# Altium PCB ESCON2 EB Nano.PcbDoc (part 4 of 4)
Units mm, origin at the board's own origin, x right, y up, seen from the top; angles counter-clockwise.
Board outline 67 x 70 mm, 6 copper layers (Top Side, Mid Layer 1, Mid Layer 2, Mid Layer 5, Mid Layer 6, Bottom Side), stack 1.48 mm thick; 293 components, 114 nets, 848 pads, 2005 vias.
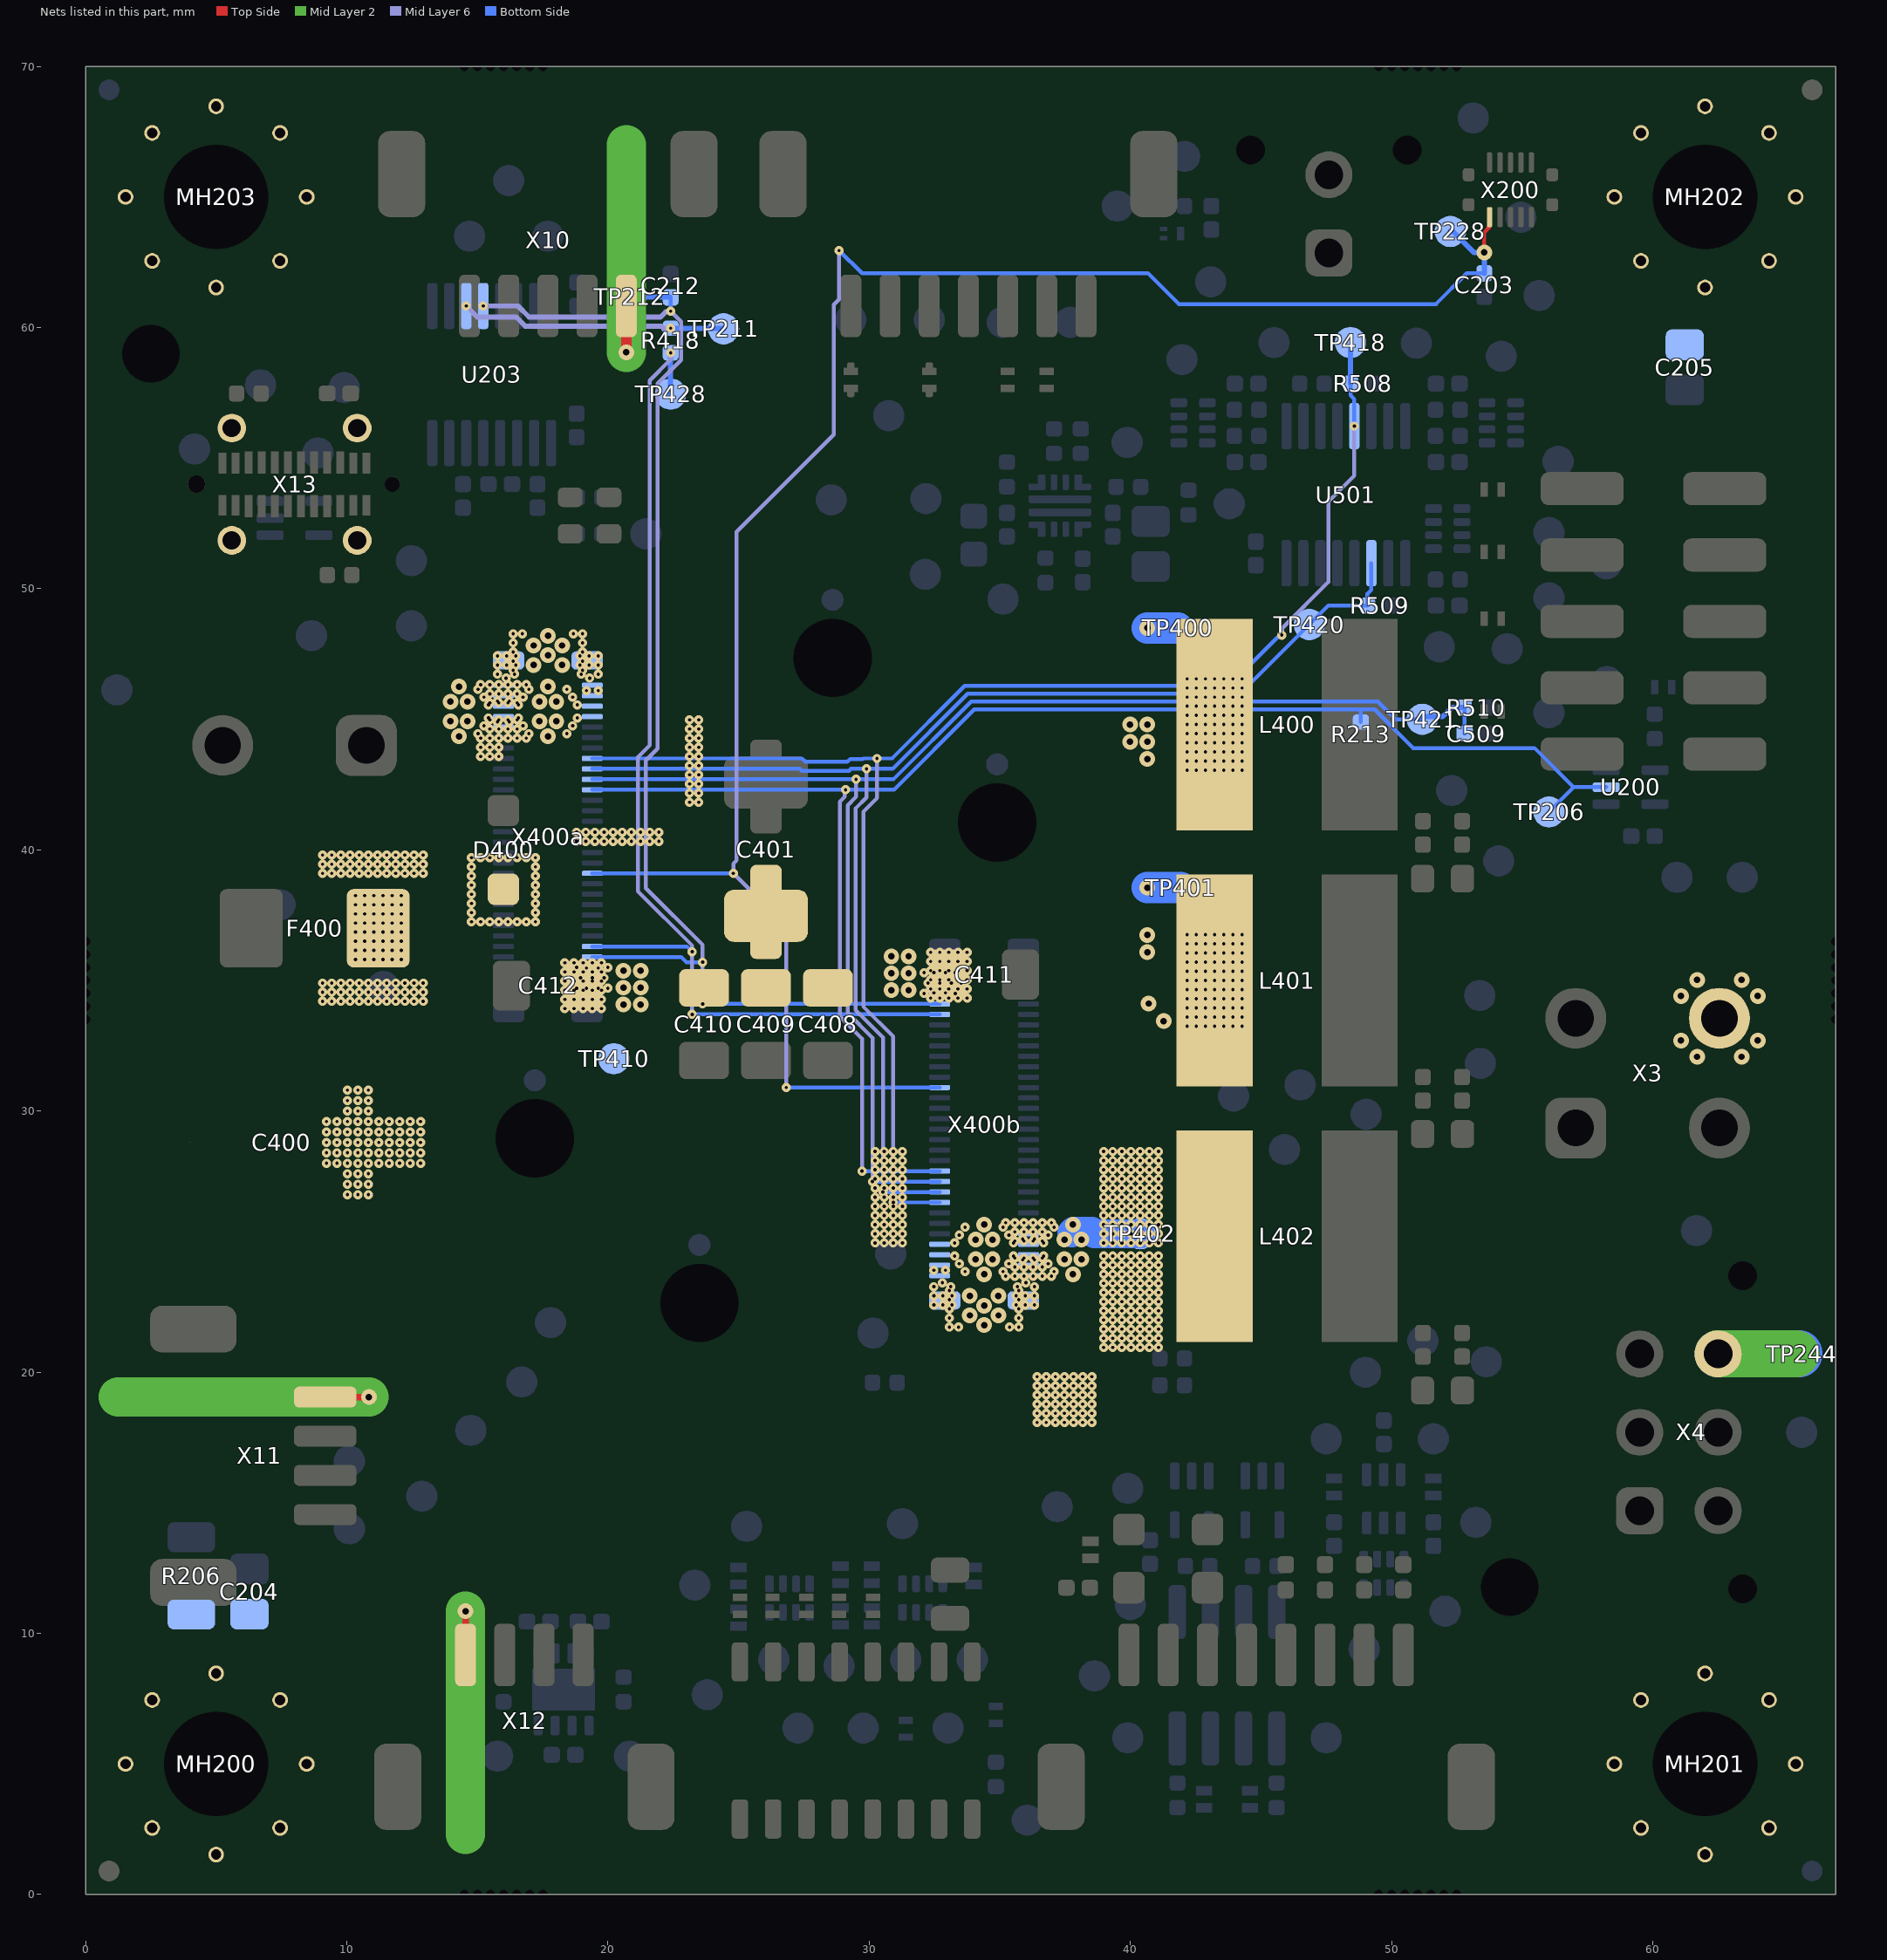
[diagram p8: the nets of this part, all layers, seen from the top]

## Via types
v1: diameter 0.35, hole 0.125, Top Side to Mid Layer 1, tented both sides, 1153 vias
v2: diameter 0.6, hole 0.25, Top Side to Bottom Side, 489 vias
v3: diameter 0.35, hole 0.125, Mid Layer 6 to Bottom Side, tented both sides, 363 vias

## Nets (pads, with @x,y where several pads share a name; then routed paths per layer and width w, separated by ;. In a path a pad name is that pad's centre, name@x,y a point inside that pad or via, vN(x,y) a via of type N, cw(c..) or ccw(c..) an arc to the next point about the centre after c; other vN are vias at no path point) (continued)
S2_B_HsDgin2: R508.1 TP418.1 U501.5 X400a.16 X400b.16 | length 60.1
  Mid Layer 6 w0.15: v3(30.3,43.5) 30.3,41.981 29.775,41.456 29.775,34.001 30.925,32.851 v3(30.925,26.5) ; v3(45.8,48.225) 45.808,48.233 45.808,48.483 47.575,50.25 47.575,53.325 48.575,54.325 v3(48.575,56.225)
  Bottom Side w0.15: X400a.16@19.4,43.5 27.429,43.5 27.559,43.37 29.168,43.37 29.273,43.475 29.749,43.475 29.774,43.5 v3(30.3,43.5) 30.877,43.5 33.652,46.275 43.775,46.275 45.63,48.13 45.651,48.13 45.746,48.225 v3(45.8,48.225) ; v3(30.925,26.5) 31.325,26.5 X400b.16@32.7,26.5 ; R508.1@48.43,57.85 48.43,57.395 48.575,57.25 v3(48.575,56.225)
  Bottom Side w0.2: TP418.1@48.425,59.175 48.43,59.17 R508.1@48.43,57.85
S2_Clock: R213.2 TP206.1 U200.2 X400a.22 X400b.22 | length 61.2
  Mid Layer 6 w0.15: v3@29.15,42.3 29.062,42.212 29.062,42.032 28.875,41.845 28.875,33.625 29.725,32.775 v3(29.725,27.7)
  Bottom Side w0.15: X400a.22@19.4,42.3 30.953,42.3 34.028,45.375 48.825,45.375 ; v3(29.725,27.7) X400b.22@32.7,27.7 ; R213.2@48.825,44.895 48.825,45.375 ; TP206.1@56.025,41.45 56.972,42.397 56.972,42.4 ; U200.2@58.215,42.4 56.972,42.4 ; 48.825,45.375 49.35,45.375 50.825,43.9 55.472,43.9 56.972,42.4
  other v3: 29.1,42.3
S2_Data_HsDgin4: C509.1 R510.2 TP421.1 X400a.20 X400b.20 | length 54.6
  Mid Layer 6 w0.15: v3(29.5,42.7) 29.5,42.032 29.175,41.707 29.175,33.751 30.125,32.801 v3(30.125,27.3)
  Bottom Side w0.15: X400a.20@19.4,42.7 29.55,42.7 30.928,42.7 33.903,45.675 49.475,45.675 50.15,45 TP421.1@51.175,45 ; v3(30.125,27.3) 30.525,27.3 X400b.20@32.7,27.3 ; R510.2@52.78,45.45 52.8,45.43 C509.1@52.8,44.45
  Bottom Side w0.2: TP421.1@51.175,45 51.274,45.099 51.949,45.099 52.3,45.45 R510.2@52.78,45.45
S2_I_HsDgin3: R509.1 TP420.1 U501.11 X400a.18 X400b.18 | length 53
  Mid Layer 6 w0.15: v3(29.9,43.1) 29.9,42.007 29.475,41.582 29.475,33.875 30.525,32.825 v3(30.525,26.9)
  Bottom Side w0.15: X400a.18@19.4,43.1 27.35,43.1 27.425,43.025 29.227,43.025 29.302,43.1 30.901,43.1 33.776,45.975 44.2,45.975 TP420.1@46.85,48.625 47.575,49.35 R509.1@49.08,49.35 49.075,49.355 49.075,49.8 49.225,49.95 U501.11@49.225,50.975 ; v3(30.525,26.9) 30.925,26.9 X400b.18@32.7,26.9
SGND: C204.2 C205.2 MH200.2 MH200.3 MH200.4 MH200.5 MH200.6 MH200.7 MH200.8 MH200.9 MH201.2 MH201.3 MH201.4 MH201.5 MH201.6 MH201.7 MH201.8 MH201.9 MH202.2 MH202.3 MH202.4 MH202.5 MH202.6 MH202.7 MH202.8 MH202.9 MH203.2 MH203.3 MH203.4 MH203.5 MH203.6 MH203.7 MH203.8 MH203.9 R206.2 TP244.1 X3.4 X4.6 X10.5 X11.4 X12.4 X13.S1 X13.S2 X13.S3 X13.S4 | length 35.5
  Top Side w0.25: X11.4@9.65,19.05 v2@10.85,19.05 ; X12.4@14.55,9.65 v2(14.55,10.85)
  Top Side w0.4: v2(20.7,59.05) X10.5@20.7,60
  Mid Layer 2 w1.5: 1.25,19.05 v2(10.85,19.05) ; 14.55,2.3 v2(14.55,10.85) ; v2(20.7,59.05) 20.7,67
  Mid Layer 2 w1.8: X4.6@62.5,20.7 65.475,20.7
  Bottom Side w1.8: X4.6@62.5,20.7 TP244.1@65.6,20.7
  other v2: 61.7,32.078 63.4,32.078 61.078,32.7 64.022,32.7 61.078,34.4 64.022,34.4 61.7,35.022 63.4,35.022
SYS_/Reset: C203.2 TP228.1 X200.10 X400a.38 X400b.38 | length 75.7
  Top Side w0.15: v2(53.55,62.875) 53.55,63.645 53.75,63.845 X200.10@53.75,64.23
  Mid Layer 6 w0.15: v3(26.825,30.9) 26.825,37.075 v3(24.8,39.1) 24.8,39.475 24.919,39.594 24.919,52.172 28.65,55.903 28.65,60.875 28.85,61.075 v3(28.85,62.95)
  Bottom Side w0.15: X400a.38@19.4,39.1 v3(24.8,39.1) ; v3(26.825,30.9) X400b.38@32.7,30.9 ; v3(28.85,62.95) 29.726,62.074 40.676,62.074 41.85,60.9 51.7,60.9 52.875,62.075 C203.2@53.55,62.075
  Bottom Side w0.2: TP228.1@52.25,63.675 52.35,63.675 53.15,62.875 v2(53.55,62.875) C203.2@53.55,62.075
U: L400.1 TP400.1 X400a.0a X400a.1 X400a.2 X400a.4 X400b.0a X400b.1 X400b.2 X400b.4 | length 1.2
  Bottom Side w1.2: v2(40.65,48.5) TP400.1@41.8,48.5
  other v1: 36.425,18.075 36.775,18.075 37.125,18.075 37.475,18.075 37.825,18.075 38.175,18.075 38.525,18.075 36.425,18.425 36.775,18.425 37.125,18.425 37.475,18.425 37.825,18.425 38.175,18.425 38.525,18.425 36.425,18.775 36.775,18.775 37.125,18.775 37.475,18.775 37.825,18.775 38.175,18.775 38.525,18.775 36.425,19.125 36.775,19.125 37.125,19.125 37.475,19.125 37.825,19.125 38.175,19.125 38.525,19.125 36.425,19.475 36.775,19.475 37.125,19.475 37.475,19.475 37.825,19.475 38.175,19.475 38.525,19.475 36.425,19.825 36.775,19.825 37.125,19.825 37.475,19.825 37.825,19.825 38.175,19.825 38.525,19.825 33.075,21.725 33.425,21.725 35.375,21.725 35.725,21.725 33.075,22.075 35.725,22.075 33.075,22.425 35.725,22.425 33.075,22.775 35.725,22.775 33.075,23.125 35.725,23.125 42.175,43.05 42.525,43.05 42.875,43.05 43.225,43.05 43.575,43.05 43.925,43.05 44.275,43.05 42.175,43.4 42.525,43.4 42.875,43.4 43.225,43.4 43.575,43.4 43.925,43.4 44.275,43.4 42.175,43.75 42.525,43.75 42.875,43.75 43.225,43.75 43.575,43.75 43.925,43.75 44.275,43.75 42.175,44.1 42.525,44.1 42.875,44.1 43.225,44.1 43.575,44.1 43.925,44.1 44.275,44.1 42.175,44.45 42.525,44.45 42.875,44.45 43.225,44.45 43.575,44.45 43.925,44.45 44.275,44.45 42.175,44.8 42.525,44.8 42.875,44.8 43.225,44.8 43.575,44.8 43.925,44.8 44.275,44.8 42.175,45.15 42.525,45.15 42.875,45.15 43.225,45.15 43.575,45.15 43.925,45.15 44.275,45.15 42.175,45.5 42.525,45.5 42.875,45.5 43.225,45.5 43.575,45.5 43.925,45.5 44.275,45.5 42.175,45.85 42.525,45.85 42.875,45.85 43.225,45.85 43.575,45.85 43.925,45.85 44.275,45.85 42.175,46.2 42.525,46.2 42.875,46.2 43.225,46.2 43.575,46.2 43.925,46.2 44.275,46.2 42.175,46.55 42.525,46.55 42.875,46.55 43.225,46.55 43.575,46.55 43.925,46.55 44.275,46.55 16.375,46.875 19.025,46.875 16.375,47.225 19.025,47.225 16.375,47.575 19.025,47.575 16.375,47.925 19.025,47.925 16.375,48.275 16.725,48.275 18.675,48.275 19.025,48.275
  other v2: 34.4,21.8 33.85,22.175 34.95,22.175 34.4,22.55 33.85,22.925 34.945,22.925 40.65,43.48 39.99,44.14 40.65,44.14 39.99,44.8 40.65,44.8 17.155,47.075 18.25,47.075 17.7,47.45 17.15,47.825 18.25,47.825 17.7,48.2
  other v3: 32.475,22.575 32.825,22.575 33.175,22.575 35.625,22.575 35.975,22.575 36.325,22.575 32.475,22.925 32.825,22.925 33.175,22.925 35.625,22.925 35.975,22.925 36.325,22.925 32.475,23.275 33.125,23.275 35.675,23.275 36.325,23.275 32.8,23.425 36,23.425 32.475,23.9 32.925,23.9 19.175,46.1 19.625,46.1 16.1,46.575 19.3,46.575 15.775,46.725 16.425,46.725 18.975,46.725 19.625,46.725 15.775,47.075 16.125,47.075 16.475,47.075 18.925,47.075 19.275,47.075 19.625,47.075 15.775,47.425 16.125,47.425 16.475,47.425 18.925,47.425 19.275,47.425 19.625,47.425
UART_RxD: C212.2 TP212.1 U203.12 X400a.54 X400b.54 | length 51.1
  Mid Layer 6 w0.15: v3(22.4,60.625) 22.8,60.225 22.8,58.75 21.9,57.85 21.9,43.878 21.45,43.428 21.45,38.532 23.625,36.357 v3(23.625,35.7) v3(23.625,34.1)
  Mid Layer 6 w0.2: v3(15.225,60.825) 16.558,60.825 16.983,60.4 22.011,60.4 22.207,60.596 22.371,60.596 v3(22.4,60.625)
  Bottom Side w0.15: X400a.54@19.4,35.9 22.8,35.9 23,35.7 v3(23.625,35.7) ; C212.2@22.375,61.175 C212.2@22.4,61.15 v3(22.4,60.625) ; v3(23.625,34.1) X400b.54@32.7,34.1
  Bottom Side w0.2: TP212.1@20.825,61.175 C212.2@22.375,61.175
UART_TxD: R418.1 TP211.1 U203.11 | length 10.2
  Mid Layer 6 w0.2: v3(14.575,60.825) 15,60.4 16.488,60.4 16.838,60.05 22.047,60.05 22.127,59.97 v3(22.4,59.97)
  Bottom Side w0.2: v3(22.4,59.97) 24.405,59.97 TP211.1@24.425,59.95
UART_TxD_n: R418.2 TP428.1 X400a.52 X400b.52 | length 41.5
  Mid Layer 6 w0.15: v3(22.4,59.03) 22.395,59.025 22.395,58.77 21.6,57.975 21.6,44.002 21.15,43.552 21.15,38.408 23.225,36.333 v3(23.225,36.1) v3(23.225,33.7)
  Bottom Side w0.15: X400a.52@19.4,36.3 23.025,36.3 v3@23.125,36.2 ; v3(23.225,33.7) X400b.52@32.7,33.7
  Bottom Side w0.2: TP428.1@22.4,57.45 v3(22.4,59.03)
V: L401.1 TP401.1 X400a.3 X400a.5 X400a.6 X400b.3 X400b.5 X400b.6 | length 1.3
  Bottom Side w1.2: v2(40.65,38.55) TP401.1@41.925,38.55
  other v1: 38.975,20.95 39.325,20.95 39.675,20.95 40.025,20.95 40.375,20.95 40.725,20.95 41.075,20.95 38.975,21.3 39.325,21.3 39.675,21.3 40.025,21.3 40.375,21.3 40.725,21.3 41.075,21.3 38.975,21.65 39.325,21.65 39.675,21.65 40.025,21.65 40.375,21.65 40.725,21.65 41.075,21.65 38.975,22 39.325,22 39.675,22 40.025,22 40.375,22 40.725,22 41.075,22 38.975,22.35 39.325,22.35 39.675,22.35 40.025,22.35 40.375,22.35 40.725,22.35 41.075,22.35 38.975,22.7 39.325,22.7 39.675,22.7 40.025,22.7 40.375,22.7 40.725,22.7 41.075,22.7 38.975,23.05 39.325,23.05 39.675,23.05 40.025,23.05 40.375,23.05 40.725,23.05 41.075,23.05 38.975,23.4 39.325,23.4 39.675,23.4 40.025,23.4 40.375,23.4 40.725,23.4 41.075,23.4 35.225,23.675 35.575,23.675 35.925,23.675 36.275,23.675 36.625,23.675 36.975,23.675 38.975,23.75 39.325,23.75 39.675,23.75 40.025,23.75 40.375,23.75 40.725,23.75 41.075,23.75 35.575,24.025 35.925,24.025 36.275,24.025 36.625,24.025 38.975,24.1 39.325,24.1 39.675,24.1 40.025,24.1 40.375,24.1 40.725,24.1 41.075,24.1 35.575,24.375 35.925,24.375 36.275,24.375 36.625,24.375 38.975,24.45 39.325,24.45 39.675,24.45 40.025,24.45 40.375,24.45 40.725,24.45 41.075,24.45 42.175,33.25 42.525,33.25 42.875,33.25 43.225,33.25 43.575,33.25 43.925,33.25 44.275,33.25 42.175,33.6 42.525,33.6 42.875,33.6 43.225,33.6 43.575,33.6 43.925,33.6 44.275,33.6 42.175,33.95 42.525,33.95 42.875,33.95 43.225,33.95 43.575,33.95 43.925,33.95 44.275,33.95 42.175,34.3 42.525,34.3 42.875,34.3 43.225,34.3 43.575,34.3 43.925,34.3 44.275,34.3 42.175,34.65 42.525,34.65 42.875,34.65 43.225,34.65 43.575,34.65 43.925,34.65 44.275,34.65 42.175,35 42.525,35 42.875,35 43.225,35 43.575,35 43.925,35 44.275,35 42.175,35.35 42.525,35.35 42.875,35.35 43.225,35.35 43.575,35.35 43.925,35.35 44.275,35.35 42.175,35.7 42.525,35.7 42.875,35.7 43.225,35.7 43.575,35.7 43.925,35.7 44.275,35.7 42.175,36.05 42.525,36.05 42.875,36.05 43.225,36.05 43.575,36.05 43.925,36.05 44.275,36.05 42.175,36.4 42.525,36.4 42.875,36.4 43.225,36.4 43.575,36.4 43.925,36.4 44.275,36.4 42.175,36.75 42.525,36.75 42.875,36.75 43.225,36.75 43.575,36.75 43.925,36.75 44.275,36.75 23.125,41.825 23.475,41.825 23.125,42.175 23.475,42.175 23.125,42.525 23.475,42.525 23.125,42.875 23.475,42.875 23.125,43.225 23.475,43.225 23.125,43.575 23.475,43.575 23.125,43.925 23.475,43.925 23.125,44.275 23.475,44.275 23.125,44.625 23.475,44.625 23.125,44.975 23.475,44.975 15.475,45.625 15.825,45.625 16.175,45.625 16.525,45.625 15.475,45.975 15.825,45.975 16.175,45.975 16.525,45.975 15.125,46.325 15.475,46.325 15.825,46.325 16.175,46.325 16.525,46.325 16.875,46.325
  other v2: 34.4,23.75 37.8,23.75 34.075,24.325 34.725,24.325 37.475,24.325 38.125,24.325 41.275,33.44 40.7,34.115 40.65,36.08 40.65,36.74 13.975,45.675 14.625,45.675 17.375,45.675 18.025,45.675 14.3,46.25 17.7,46.25
  other v3: 33.675,23.85 35.125,23.85 37.075,23.85 33.45,24.15 35.35,24.15 36.85,24.15 35.875,24.3 36.325,24.3 33.275,24.45 35.525,24.45 36.675,24.45 15.425,45.55 16.575,45.55 18.825,45.55 15.775,45.7 16.225,45.7 15.25,45.85 16.75,45.85 18.65,45.85 15.025,46.15 16.975,46.15 18.425,46.15
VP: C400.1 C401.1 C408.2 C409.2 C410.2 C411.2 C412.2 D400.1 F400.2 TP410.1 X400a.56 X400a.58 X400a.60 X400b.56 X400b.58 X400b.60
  other v1: 10.025,26.8 10.425,26.8 10.825,26.8 10.025,27.2 10.425,27.2 10.825,27.2 10.025,27.6 10.425,27.6 10.825,27.6 9.225,28 9.625,28 10.025,28 10.425,28 10.825,28 11.225,28 11.625,28 12.025,28 12.425,28 12.825,28 9.225,28.4 9.625,28.4 10.025,28.4 10.425,28.4 10.825,28.4 11.225,28.4 11.625,28.4 12.025,28.4 12.425,28.4 12.825,28.4 9.225,28.8 9.625,28.8 10.025,28.8 10.425,28.8 10.825,28.8 11.225,28.8 11.625,28.8 12.025,28.8 12.425,28.8 12.825,28.8 9.225,29.2 9.625,29.2 10.025,29.2 10.425,29.2 10.825,29.2 11.225,29.2 11.625,29.2 12.025,29.2 12.425,29.2 12.825,29.2 9.225,29.6 9.625,29.6 10.025,29.6 10.425,29.6 10.825,29.6 11.225,29.6 11.625,29.6 12.025,29.6 12.425,29.6 12.825,29.6 10.025,30 10.425,30 10.825,30 10.025,30.4 10.425,30.4 10.825,30.4 10.025,30.8 10.425,30.8 10.825,30.8 18.35,33.925 18.7,33.925 19.05,33.925 19.4,33.925 19.75,33.925 9.075,34.2 9.425,34.2 9.775,34.2 10.125,34.2 10.475,34.2 10.825,34.2 11.175,34.2 11.525,34.2 11.875,34.2 12.225,34.2 12.575,34.2 12.925,34.2 18.35,34.275 18.7,34.275 19.05,34.275 19.4,34.275 19.75,34.275 32.35,34.325 32.7,34.325 33.05,34.325 33.4,34.325 33.75,34.325 9.075,34.55 9.425,34.55 9.775,34.55 10.125,34.55 10.475,34.55 10.825,34.55 11.175,34.55 11.525,34.55 11.875,34.55 12.225,34.55 12.575,34.55 12.925,34.55 18.35,34.625 18.7,34.625 19.05,34.625 19.4,34.625 19.75,34.625 32.35,34.675 32.7,34.675 33.05,34.675 33.4,34.675 33.75,34.675 9.075,34.9 9.425,34.9 9.775,34.9 10.125,34.9 10.475,34.9 10.825,34.9 11.175,34.9 11.525,34.9 11.875,34.9 12.225,34.9 12.575,34.9 12.925,34.9 18.35,34.975 18.7,34.975 19.05,34.975 19.4,34.975 19.75,34.975 32.35,35.025 32.7,35.025 33.05,35.025 33.4,35.025 33.75,35.025 18.35,35.325 18.7,35.325 19.05,35.325 19.4,35.325 19.75,35.325 32.35,35.375 32.7,35.375 33.05,35.375 33.4,35.375 33.75,35.375 18.35,35.675 18.7,35.675 19.05,35.675 19.4,35.675 19.75,35.675 32.35,35.725 32.7,35.725 33.05,35.725 33.4,35.725 33.75,35.725 10.335,35.8 10.685,35.8 11.035,35.8 11.385,35.8 11.735,35.8 12.085,35.8 32.35,36.075 32.7,36.075 33.05,36.075 33.4,36.075 33.75,36.075 10.335,36.15 10.685,36.15 11.035,36.15 11.385,36.15 11.735,36.15 12.085,36.15 10.335,36.5 10.685,36.5 11.035,36.5 11.385,36.5 11.735,36.5 12.085,36.5 10.335,36.85 10.685,36.85 11.035,36.85 11.385,36.85 11.735,36.85 12.085,36.85 10.335,37.2 10.685,37.2 11.035,37.2 11.385,37.2 11.735,37.2 12.085,37.2 14.775,37.25 15.125,37.25 15.475,37.25 15.825,37.25 16.175,37.25 16.525,37.25 16.875,37.25 17.225,37.25 10.335,37.55 10.685,37.55 11.035,37.55 11.385,37.55 11.735,37.55 12.085,37.55 14.775,37.6 17.225,37.6 10.335,37.9 10.685,37.9 11.035,37.9 11.385,37.9 11.735,37.9 12.085,37.9 14.775,37.95 17.225,37.95 10.335,38.25 10.685,38.25 11.035,38.25 11.385,38.25 11.735,38.25 12.085,38.25 14.775,38.3 17.225,38.3 14.775,38.65 17.225,38.65 14.775,39 17.225,39 9.075,39.1 9.425,39.1 9.775,39.1 10.125,39.1 10.475,39.1 10.825,39.1 11.175,39.1 11.525,39.1 11.875,39.1 12.225,39.1 12.575,39.1 12.925,39.1 14.775,39.35 17.225,39.35 9.075,39.45 9.425,39.45 9.775,39.45 10.125,39.45 10.475,39.45 10.825,39.45 11.175,39.45 11.525,39.45 11.875,39.45 12.225,39.45 12.575,39.45 12.925,39.45 14.775,39.7 15.125,39.7 15.475,39.7 15.825,39.7 16.175,39.7 16.525,39.7 16.875,39.7 17.225,39.7 9.075,39.8 9.425,39.8 9.775,39.8 10.125,39.8 10.475,39.8 10.825,39.8 11.175,39.8 11.525,39.8 11.875,39.8 12.225,39.8 12.575,39.8 12.925,39.8
  other v2: 20.59,34.075 21.25,34.075 30.85,34.625 31.51,34.625 20.59,34.725 21.25,34.725 30.85,35.275 31.51,35.275 20.59,35.375 21.25,35.375 30.85,35.925 31.51,35.925
  other v3: 32.1,34.5 33.3,34.5 32.475,34.525 32.925,34.525 18.8,34.7 19.175,34.7 19.625,34.7 20,34.7 32.25,34.9 32.7,34.9 33.15,34.9 33.525,34.9 18.575,35.1 18.95,35.1 19.4,35.1 19.85,35.1 32.1,35.3 32.475,35.3 32.925,35.3 33.3,35.3 19.175,35.475 19.625,35.475 18.8,35.5 20,35.5
W: L402.1 TP402.1 X400a.7 X400a.8 X400a.9 X400b.7 X400b.8 X400b.9 | length 2.7
  Bottom Side w1.1: 37.75,25.325 37.825,25.4 38.525,25.4 38.625,25.3 v1(40.375,25.3)
  other v1: 30.225,24.95 30.575,24.95 30.925,24.95 31.275,24.95 38.975,24.95 39.325,24.95 39.675,24.95 40.025,24.95 40.375,24.95 40.725,24.95 41.075,24.95 35.575,25.025 35.925,25.025 36.275,25.025 36.625,25.025 30.225,25.3 30.575,25.3 30.925,25.3 31.275,25.3 38.975,25.3 39.325,25.3 39.675,25.3 40.025,25.3 40.725,25.3 41.075,25.3 35.575,25.375 35.925,25.375 36.275,25.375 36.625,25.375 30.225,25.65 30.575,25.65 30.925,25.65 31.275,25.65 38.975,25.65 39.325,25.65 39.675,25.65 40.025,25.65 40.375,25.65 40.725,25.65 41.075,25.65 35.225,25.725 35.575,25.725 35.925,25.725 36.275,25.725 36.625,25.725 36.975,25.725 30.225,26 30.575,26 30.925,26 31.275,26 38.975,26 39.325,26 39.675,26 40.025,26 40.375,26 40.725,26 41.075,26 30.225,26.35 30.575,26.35 30.925,26.35 31.275,26.35 38.975,26.35 39.325,26.35 39.675,26.35 40.025,26.35 40.375,26.35 40.725,26.35 41.075,26.35 30.225,26.7 30.575,26.7 30.925,26.7 31.275,26.7 38.975,26.7 39.325,26.7 39.675,26.7 40.025,26.7 40.375,26.7 40.725,26.7 41.075,26.7 30.225,27.05 30.575,27.05 30.925,27.05 31.275,27.05 38.975,27.05 39.325,27.05 39.675,27.05 40.025,27.05 40.375,27.05 40.725,27.05 41.075,27.05 30.225,27.4 30.575,27.4 30.925,27.4 31.275,27.4 38.975,27.4 39.325,27.4 39.675,27.4 40.025,27.4 40.375,27.4 40.725,27.4 41.075,27.4 30.225,27.75 30.575,27.75 30.925,27.75 31.275,27.75 38.975,27.75 39.325,27.75 39.675,27.75 40.025,27.75 40.375,27.75 40.725,27.75 41.075,27.75 30.225,28.1 30.575,28.1 30.925,28.1 31.275,28.1 38.975,28.1 39.325,28.1 39.675,28.1 40.025,28.1 40.375,28.1 40.725,28.1 41.075,28.1 30.225,28.45 30.575,28.45 30.925,28.45 31.275,28.45 38.975,28.45 39.325,28.45 39.675,28.45 40.025,28.45 40.375,28.45 40.725,28.45 41.075,28.45 18.8,40.325 19.15,40.325 19.5,40.325 19.85,40.325 20.2,40.325 20.55,40.325 20.9,40.325 21.25,40.325 21.6,40.325 21.95,40.325 18.8,40.675 19.15,40.675 19.5,40.675 19.85,40.675 20.2,40.675 20.55,40.675 20.9,40.675 21.25,40.675 21.6,40.675 21.95,40.675 15.125,43.575 15.475,43.575 15.825,43.575 15.125,43.925 15.475,43.925 15.825,43.925 15.125,44.275 15.475,44.275 15.825,44.275 16.175,44.275 16.525,44.275 16.875,44.275 15.475,44.625 15.825,44.625 16.175,44.625 16.525,44.625 15.475,44.975 15.825,44.975 16.175,44.975 16.525,44.975
  other v2: 34.075,25.075 34.725,25.075 37.475,25.075 38.125,25.075 34.4,25.65 37.8,25.65 14.3,44.35 17.7,44.35 13.975,44.925 14.625,44.925 17.375,44.925 18.025,44.925
  other v3: 33.275,24.95 35.525,24.95 36.675,24.95 35.875,25.1 36.325,25.1 33.45,25.25 35.35,25.25 36.85,25.25 33.675,25.55 35.125,25.55 37.075,25.55 15.025,44.45 16.975,44.45 18.425,44.45 15.25,44.75 16.75,44.75 18.65,44.75 15.775,44.9 16.225,44.9 15.425,45.05 16.575,45.05 18.825,45.05
pads on no net: FD200.1 FD201.1 FD202.1 FD203.1 MH200.1 MH201.1 MH202.1 MH203.1 MH204.1 MH205.1 MP400.0 MP401.0 MP402.0 MP403.0 RN501.3 RN501.6 RN502.2 RN502.7 RN503.2 RN503.7 RN504.2 RN504.7 STEG200.0 STEG201.0 STEG202.0 STEG203.0 STEG204.0 STEG205.0 U200.1 U203.7 U203.9 U400.3 U400.4 U400.10 U501.13 U501.14 U501.15 X4.0 X5.9 X7.0 X8.0 X10.0 X11.0 X12.0 X13.0 X13.A2 X13.A3 X13.A8 X13.A10 X13.A11 X13.B2 X13.B3 X13.B8 X13.B10 X13.B11 X16.0 X200.0 X200.6 X200.7 X200.8

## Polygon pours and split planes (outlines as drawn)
GND on Bottom Side "B_GND-001" (solid, remove dead copper, pour order 415): 0,0 0,70 67,70 67,0
5V0 on Bottom Side "BOT_5V0" (solid, remove dead copper, pour order 412): 31.525,52.275 34.686,52.261 34.9,52.475 35.325,52.475 35.9,52.475 35.9,53.05 36.075,53.225 39.875,53.225 39.875,54.575 39.25,54.575 38.45,53.775 36.15,53.775 35.3,54.625 31.525,54.625
C_W2 on Bottom Side "BOT_C_W2-002" (solid, remove dead copper, pour order 314): 54.9,36.35 59.7,36.35 59.7,31.55 54.9,31.55
W on Bottom Side "B_W_n_2" (solid, remove dead copper, pour order 241): 38.475,25.425 38.475,24.775 32.3,24.775 32.3,25.425
W on Bottom Side "B_W_n" (solid, remove dead copper, pour order 82): 13.625,44.575 13.625,45.225 19.8,45.225 19.8,44.575
C_VP on Bottom Side "B_C_VP-001" (solid, remove dead copper, pour order 362): 7.9,41.2 0,41.2 0,46.8 7.9,46.8
SGND on Bottom Side "B_SGND-002" (solid, pour order 377): 1.53,5 2.55,7.45 5,8.47 7.45,7.45 8.47,5 8.476,5 8.476,7.849 8.475,7.85 7.45,11.4 0.5,11.4 0.5,5
SGND on Bottom Side "B_SGND-003" (solid, pour order 378): 65.47,65 64.45,62.55 62,61.53 59.55,62.55 58.53,65 58.524,65 58.524,62.15 59.95,58.75 66.5,58.75 66.5,65
SGND on Bottom Side "B_SGND-001" (solid, remove dead copper, pour order 372): 60.1,36.35 64.7,36.35 64.7,31.55 60.1,31.55
C_W3 on Bottom Side "BOT_C_W3-002" (solid, remove dead copper, pour order 318): 59.9,31.35 64.7,31.35 64.7,26.55 59.9,26.55
C_W1 on Bottom Side "BOT_C_W1-002" (solid, remove dead copper, pour order 248): 54.9,31.35 59.7,31.35 59.7,26.55 54.9,26.55
5V0_sensor1_2 on Bottom Side "B_5V0_sensor1_2-001" (solid, remove dead copper, pour order 5): 42.55,53.45 40.025,53.45 40.025,54.575 42.55,54.575
V on Bottom Side "B_V_n" (solid, remove dead copper, pour order 81): 18.288,46.55 18.875,45.963 18.875,45.375 16.525,45.375 16.525,45.962 17.113,46.55
V on Bottom Side "B_V_n" (solid, remove dead copper, pour order 83): 13.625,45.375 13.625,46.025 19.8,46.025 19.8,45.375
W on Bottom Side "B_W_n" (solid, remove dead copper, pour order 84): 17.113,44.05 16.525,44.638 16.525,45.225 18.875,45.225 18.875,44.638 18.287,44.05
W on Bottom Side "B_W_n" (solid, remove dead copper, pour order 85): 13.713,44.05 13.625,44.138 13.625,45.225 15.475,45.225 15.475,44.638 14.888,44.05
V on Bottom Side "B_V_n" (solid, remove dead copper, pour order 87): 13.713,46.55 13.625,46.462 13.625,45.375 15.475,45.375 15.475,45.962 14.888,46.55
U on Bottom Side "B_U_n" (solid, remove dead copper, pour order 147): 15.6,45.775 15.6,47.875 19.8,47.875 19.8,45.775
U on Bottom Side "B_U_n" (solid, remove dead copper, pour order 239): 18.163,48.525 18.875,47.813 18.875,47.55 16.525,47.55 16.525,47.813 17.238,48.525
V on Bottom Side "B_V_n_2" (solid, remove dead copper, pour order 240): 33.812,23.45 33.225,24.037 33.225,24.625 35.575,24.625 35.575,24.038 34.987,23.45
V on Bottom Side "B_V_n_2" (solid, remove dead copper, pour order 242): 38.475,24.625 38.475,23.975 32.3,23.975 32.3,24.625
W on Bottom Side "B_W_n_2" (solid, remove dead copper, pour order 247): 34.987,25.95 35.575,25.362 35.575,24.775 33.225,24.775 33.225,25.362 33.813,25.95
W on Bottom Side "B_W_n_2" (solid, remove dead copper, pour order 327): 38.387,25.95 38.475,25.862 38.475,24.775 36.625,24.775 36.625,25.362 37.212,25.95
V on Bottom Side "B_V_n_2" (solid, remove dead copper, pour order 329): 38.387,23.45 38.475,23.538 38.475,24.625 36.625,24.625 36.625,24.038 37.212,23.45
U on Bottom Side "B_U_n_2" (solid, remove dead copper, pour order 348): 36.5,24.225 36.5,22.125 32.3,22.125 32.3,24.225
U on Bottom Side "B_U_n_2" (solid, remove dead copper, pour order 356): 33.938,21.475 33.225,22.187 33.225,22.45 35.575,22.45 35.575,22.187 34.862,21.475
VP on Bottom Side "B_VP_n" (solid, remove dead copper, pour order 357): 21.55,31.4 19.625,31.4 19.625,33.775 17.775,33.775 17.775,35.675 21.55,35.675 21.55,33.775
GND on Bottom Side "B_GND_n" (solid, pour order 358): 17.625,35.675 17.625,33.775 13.85,33.775 13.85,35.675
VP on Bottom Side "B_VP_n_2" (solid, remove dead copper, pour order 359): 34.325,36.225 34.325,34.325 30.55,34.325 30.55,36.225
GND on Bottom Side "B_GND_n_2" (solid, pour order 360): 34.475,34.325 34.475,36.225 38.25,36.225 38.25,34.325
NetC415_2 on Bottom Side "BOT_5V0_sensor1_2" (solid, remove dead copper, pour order 411): 36.1,53.1 36.1,52.575 38.45,52.575 38.6,52.425 39.675,52.425 39.875,52.225 42.55,52.225 42.55,53.3 40.95,53.3 40.025,53.3 39,53.3 38.8,53.1
GND on Mid Layer 6 "M6_GND-001" (solid, remove dead copper, pour order 416): 0,0 0,70 67,70 67,0
5V0_sensor1_2 on Mid Layer 6 "M6_5V0_sensor1_2-001" (solid, remove dead copper, pour order 29): 43.9,51.875 43.075,51.05 41.225,51.05 41.225,52.075 42.547,52.075 42.55,52.072 42.55,53.45 40.025,53.45 40.025,54.625 43.075,54.625 43.9,53.8
NetC415_2 on Mid Layer 6 "M6_5V0_sensor1_2" (solid, remove dead copper, pour order 413): 36.1,53.1 36.1,52.575 38.45,52.575 38.8,52.225 39.875,52.225 42.55,52.225 42.55,53.3 40.95,53.3 40.025,53.3 39,53.3 38.8,53.1
W on Mid Layer 6 "M6_W_n" (solid, remove dead copper, pour order 72): 13.625,44.575 13.625,45.225 19.05,45.225 19.05,44.575
V on Mid Layer 6 "M6_V_n" (solid, remove dead copper, pour order 73): 13.625,45.375 13.625,46.025 18.8,46.025 18.8,45.375
W on Mid Layer 6 "M6_W_n" (solid, remove dead copper, pour order 75): 17.113,44.05 16.525,44.638 16.525,45.225 18.875,45.225 18.875,44.638 18.287,44.05
V on Mid Layer 6 "M6_V_n" (solid, remove dead copper, pour order 77): 18.288,46.55 19.05,45.788 19.05,45.375 16.525,45.375 16.525,45.962 17.113,46.55
W on Mid Layer 6 "M6_W_n" (solid, remove dead copper, pour order 78): 13.713,44.05 13.625,44.138 13.625,45.225 15.475,45.225 15.475,44.638 14.888,44.05
V on Mid Layer 6 "M6_V_n" (solid, remove dead copper, pour order 79): 13.713,46.55 13.625,46.462 13.625,45.375 15.475,45.375 15.475,45.962 14.888,46.55
U on Mid Layer 6 "M6_U_n" (solid, remove dead copper, pour order 159): 15.6,45.775 15.6,47.875 19.8,47.875 19.8,45.775
U on Mid Layer 6 "M6_U_n" (solid, remove dead copper, pour order 243): 18.163,48.525 18.875,47.813 18.875,47.55 16.525,47.55 16.525,47.813 17.238,48.525
W on Mid Layer 6 "M6_W_n_2" (solid, remove dead copper, pour order 244): 38.475,25.425 38.475,24.775 33.05,24.775 33.05,25.425
V on Mid Layer 6 "M6_V_n_2" (solid, remove dead copper, pour order 315): 38.475,24.625 38.475,23.975 33.3,23.975 33.3,24.625
W on Mid Layer 6 "M6_W_n_2" (solid, remove dead copper, pour order 316): 34.987,25.95 35.575,25.362 35.575,24.775 33.225,24.775 33.225,25.362 33.813,25.95
V on Mid Layer 6 "M6_V_n_2" (solid, remove dead copper, pour order 332): 33.812,23.45 33.05,24.212 33.05,24.625 35.575,24.625 35.575,24.038 34.987,23.45
W on Mid Layer 6 "M6_W_n_2" (solid, remove dead copper, pour order 349): 38.387,25.95 38.475,25.862 38.475,24.775 36.625,24.775 36.625,25.362 37.212,25.95
V on Mid Layer 6 "M6_V_n_2" (solid, remove dead copper, pour order 350): 38.387,23.45 38.475,23.538 38.475,24.625 36.625,24.625 36.625,24.038 37.212,23.45
U on Mid Layer 6 "M6_U_n_2" (solid, remove dead copper, pour order 351): 36.5,24.225 36.5,22.125 32.3,22.125 32.3,24.225
U on Mid Layer 6 "M6_U_n_2" (solid, remove dead copper, pour order 352): 33.938,21.475 33.225,22.187 33.225,22.45 35.575,22.45 35.575,22.187 34.862,21.475
VP on Mid Layer 6 "M6_VP_n" (solid, remove dead copper, pour order 353): 17.775,33.775 17.775,35.675 21.55,35.675 21.55,33.775
GND on Mid Layer 6 "M6_GND_n" (solid, remove dead copper, pour order 354): 17.625,35.675 17.625,33.775 13.85,33.775 13.85,35.675
VP on Mid Layer 6 "M6_VP_n_2" (solid, remove dead copper, pour order 355): 34.325,36.225 34.325,34.325 30.55,34.325 30.55,36.225
GND on Mid Layer 6 "M6_GND_n_2" (solid, remove dead copper, pour order 380): 34.475,34.325 34.475,36.225 38.25,36.225 38.25,34.325
5V0 on Mid Layer 6 "M6_5V0" (solid, remove dead copper, pour order 414): 33.925,52.264 34.686,52.261 34.9,52.475 35.325,52.475 35.9,52.475 35.9,53.05 36.075,53.225 39.875,53.225 39.875,54.625 39.3,54.625 35.3,54.625 33.925,54.625
C_W3 on Top Side "TOP_C_W3" (solid, remove dead copper, pour order 406): 47.3,21.15 57.475,21.15 58.325,22 67,22 67,31.35 59.9,31.35 59.9,26.55 54.7,26.55 52,29.25 47.3,29.25
GND on Top Side "T_GND-001" (solid, remove dead copper, pour order 410): 0,0 0,70 67,70 67,0
C_W1 on Top Side "TOP_C_W1" (solid, remove dead copper, pour order 408): 47.3,48.85 47.3,40.75 53.45,40.75 53.45,45.625 50.225,48.85
C_W2 on Top Side "TOP_C_W2" (solid, remove dead copper, pour order 407): 47.3,30.95 54.3,30.95 54.9,31.55 59.7,31.55 59.7,39.05 47.3,39.05
U on Top Side "TOP_U_n" (solid, remove dead copper, pour order 404): 16.2,48.625 16.2,46.7 22.75,46.7 27,50.95 30.15,50.95 34.4,46.7 40.35,40.75 45.1,40.75 45.1,48.85 39.8,48.85 35.7,52.95 20.525,52.95
VP on Top Side "TOP_VP" (solid, remove dead copper, pour order 391): 8.875,40 8.875,33.8 7.5,33.8 7.5,25.75 13.55,25.75 21.1,33.3 33.925,33.3 34.325,33.7 34.325,37.125 33.6,37.85 29.3,37.85 27.15,40
C_W1 on Top Side "T_C_W1-004" (solid, remove dead copper, pour order 305): 54.9,31.35 59.7,31.35 59.7,26.55 54.9,26.55
GND on Top Side "TOP_GND_pwr" (solid, remove dead copper, pour order 403): 30.075,50.8 38.35,42.525 38.35,29.425 22.65,29.425 18.025,24.8 0,24.8 0,46.8 13.675,46.8 13.675,44.05 17.703,40.022 17.703,40.008 23.917,40.008 23.925,40 23.925,47.6 27.125,50.8
C_VP on Top Side "T_C_VP-001" (solid, remove dead copper, pour order 366): 7.9,39.95 1.9,39.95 1.9,46.8 7.9,46.8
SGND on Top Side "T_SGND-001" (solid, remove dead copper, pour order 367): 60.1,36.35 64.7,36.35 64.7,31.55 60.1,31.55
C_W2 on Top Side "T_C_W2-004" (solid, remove dead copper, pour order 321): 54.9,36.35 59.7,36.35 59.7,31.55 54.9,31.55
C_W3 on Top Side "T_C_W3-004" (solid, remove dead copper, pour order 309): 59.9,31.35 64.7,31.35 64.7,26.55 59.9,26.55
V on Top Side "T_V_n" (solid, remove dead copper, pour order 120): 18.325,45.375 13.675,45.375 13.675,46.55 18.325,46.55
W on Top Side "T_W_n" (solid, remove dead copper, pour order 121): 18.325,44.05 13.675,44.05 13.675,45.225 18.325,45.225
U on Top Side "T_U_n" (solid, remove dead copper, pour order 122): 16.2,46.7 16.2,48.625 19.2,48.625 19.2,46.7
V on Top Side "T_V_n_2" (solid, remove dead copper, pour order 161): 33.775,24.625 38.425,24.625 38.425,23.45 33.775,23.45
W on Top Side "T_W_n_2" (solid, remove dead copper, pour order 162): 28.85,29.25 44.675,29.25 44.675,24.775 28.85,24.775
U on Top Side "T_U_n_2" (solid, remove dead copper, pour order 163): 35.9,23.3 35.9,21.375 32.9,21.375 32.9,23.3
GND on Top Side "TOP_GND_n" (solid, remove dead copper, pour order 303): 17.25,35.85 17.25,33.75 13.85,33.75 13.85,35.85
C_VP on Top Side "T_C_VP-002" (solid, remove dead copper, pour order 365): 1.9,36.54 ccw(c4.44,36.54) 4.44,34 8.675,34 8.675,40 1.9,40
V on Top Side "T_V_n_2" (solid, remove dead copper, pour order 393): 33.775,23.45 35.95,23.45 38.775,20.625 41.375,20.625 41.375,24.625 33.775,24.625
W on Top Side "TOP_W_n" (solid, remove dead copper, pour order 399): 13.675,45.225 13.675,44.05 14.9,42.825 16.525,42.825 17.55,41.8 17.55,40.139 23.426,40.139 18.34,45.225 17.05,45.225
V on Top Side "TOP_V_n" (solid, remove dead copper, pour order 400): 13.675,46.55 13.675,45.375 18.425,45.375 23.775,40.025 23.775,45.75 22.975,46.55 18.325,46.55
V on Top Side "TOP_V" (solid, remove dead copper, pour order 402): 45.675,39.05 38.5,39.05 38.5,30.95 45.675,30.95
U on Top Side "TOP_U_n_2" (solid, remove dead copper, pour order 405): 32.9,23.3 35.9,23.3 38.725,20.475 38.725,17.875 35.7,17.875 32.9,20.675
GND on Mid Layer 1 "M1_GND-001" (solid, remove dead copper, pour order 409): 0,0 0,70 67,70 67,0
C_VP on Mid Layer 1 "M1_C_VP-001" (solid, remove dead copper, pour order 368): 7.9,39.95 1.9,39.95 1.9,46.8 7.9,46.8
C_W1 on Mid Layer 1 "M1_C_W1" (solid, remove dead copper, pour order 398): 46.925,48.85 46.925,44.1 50.275,40.75 50.275,26.325 59.7,26.325 59.7,31.35 54.9,31.35 54.75,31.5 54.75,44.775 50.675,48.85
SGND on Mid Layer 1 "M1_SGND-001" (solid, remove dead copper, pour order 306): 60.1,36.35 64.7,36.35 64.7,31.55 60.1,31.55
C_W3 on Mid Layer 1 "M1_C_W3-004" (solid, remove dead copper, pour order 302): 59.9,31.35 64.7,31.35 64.7,26.55 59.9,26.55
C_W2 on Mid Layer 1 "M1_C_W2-004" (solid, remove dead copper, pour order 252): 54.9,36.35 59.7,36.35 59.7,31.55 54.9,31.55
C_W1 on Mid Layer 1 "M1_C_W1-004" (solid, remove dead copper, pour order 185): 54.9,31.35 59.7,31.35 59.7,26.55 54.9,26.55
U on Mid Layer 1 "M1_U_n" (solid, remove dead copper, pour order 113): 16.2,46.7 16.2,48.625 19.2,48.625 19.2,46.7
V on Mid Layer 1 "M1_V_n" (solid, remove dead copper, pour order 137): 18.325,45.375 13.675,45.375 13.675,46.55 18.325,46.55
W on Mid Layer 1 "M1_W_n" (solid, remove dead copper, pour order 140): 18.325,44.05 13.675,44.05 13.675,45.225 18.325,45.225
U on Mid Layer 1 "M1_U_n_2" (solid, remove dead copper, pour order 165): 35.9,23.3 35.9,21.375 32.9,21.375 32.9,23.3
V on Mid Layer 1 "M1_V_n_2" (solid, remove dead copper, pour order 170): 33.775,24.625 38.425,24.625 38.425,23.45 33.775,23.45
W on Mid Layer 1 "M1_W_n_2" (solid, remove dead copper, pour order 175): 33.775,25.95 38.425,25.95 38.425,24.775 33.775,24.775
VP on Mid Layer 1 "M1_VP_n_2" (solid, remove dead copper, pour order 180): 34.325,36.25 34.325,34.15 30.55,34.15 30.55,36.25
GND on Mid Layer 1 "M1_GND_n" (solid, remove dead copper, pour order 342): 17.25,35.85 17.25,33.75 13.85,33.75 13.85,35.85
GND on Mid Layer 1 "M1_GND_n_2" (solid, remove dead copper, pour order 364): 34.475,34.15 34.475,36.25 38.25,36.25 38.25,34.15
C_VP on Mid Layer 1 "M1_C_VP-002" (solid, remove dead copper, pour order 369): 1.9,36.54 ccw(c4.44,36.54) 4.44,34 8.675,34 8.675,40 1.9,40
V on Mid Layer 1 "M1_V_n_2" (solid, remove dead copper, pour order 376): 45.675,39.05 41.675,39.05 41.675,24.775 41.525,24.625 33.775,24.625 33.775,23.45 35.95,23.45 38.775,20.625 43.275,20.625 45.675,23.025
W on Mid Layer 1 "M1_W_n_2" (solid, remove dead copper, pour order 385): 33.775,24.775 41.475,24.775 41.475,29.25 38.8,29.25 35.5,25.95 33.775,25.95
U on Mid Layer 1 "M1_U_n_2" (solid, remove dead copper, pour order 390): 32.9,23.3 35.9,23.3 38.725,20.475 43.35,20.475 45.825,22.95 45.825,39.35 42.775,42.4 42.775,48.85 46.775,48.85 46.775,44.025 50.125,40.675 50.125,21.625 44.975,16.475 37.1,16.475 32.9,20.675
W on Mid Layer 1 "M1_W_n" (solid, remove dead copper, pour order 392): 13.675,45.225 13.675,44.05 21.7,36.025 21.7,30.313 27.238,24.774 27.239,24.775 39.65,24.775 39.65,29.25 28.625,29.25 25.925,31.95 25.925,37.675 18.375,45.225
V on Mid Layer 1 "M1_V_n" (solid, remove dead copper, pour order 394): 13.675,46.55 13.675,45.375 18.425,45.375 26.075,37.725 26.075,32.025 28.7,29.4 45.675,29.4 45.675,39.05 37.325,39.05 35.475,40.9 28.625,40.9 22.975,46.55 18.325,46.55
U on Mid Layer 1 "M1_U_n" (solid, remove dead copper, pour order 395): 16.2,48.625 16.2,46.7 23.025,46.7 28.675,41.05 35.625,41.05 37.475,39.2 46.775,39.2 46.775,48.85 39.8,48.85 34.175,54.475 22.05,54.475
VP on Mid Layer 1 "M1_VP_n" (solid, remove dead copper, pour order 396): 17.775,33.3 17.775,36.3 21.55,36.3 21.55,33.3
VP on Mid Layer 1 "M1_VP" (solid, remove dead copper, pour order 397): 8.875,40 8.875,33.8 7.5,33.8 7.5,25.75 13.55,25.75 21.1,33.3 21.55,33.3 21.55,40
SGND on Mid Layer 2 "M2_SGND-001" (solid, remove dead copper, pour order 335): 0,0 0,70 67,70 67,0
SGND on Mid Layer 2 "M2_SGND-003" (solid, remove dead copper, pour order 330): 0,56.7 10.95,56.7 10.95,51.3 0,51.3
SGND on Mid Layer 2 "M2_SGND-002" (solid, remove dead copper, pour order 325): 60.1,35.5 67,35.5 67,31.55 60.1,31.55
GND on Mid Layer 2 "M2_GND-001" (solid, pour order 333): 5.001,7.46 7.467,5 59.525,5 62,7.475 62,62.525 59.525,65 7.47,65 5,62.53 5,7.47
GND on Mid Layer 5 "M5_GND-001" (solid, pour order 331): 0,0 67,0 67,70 0,70

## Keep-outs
Top Side:
  region: 47.162,21.15 47.162,29.25 44.838,29.25 44.838,21.15
  region: 47.162,30.95 47.162,39.05 44.838,39.05 44.838,30.95
  region: 47.162,40.75 47.162,48.85 44.838,48.85 44.838,40.75

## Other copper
Top Side:
  text "'.Layer_Name'" at 89,69.355 h2
Mid Layer 1:
  text "'.Layer_Name'" at 89,67.375 h2
Mid Layer 2:
  text "'.Layer_Name'" at 89,65.375 h2
Mid Layer 6:
  text "'.Layer_Name'" at 89,57.375 h2
Mid Layer 5:
  text "'.Layer_Name'" at 89,59.375 h2
Bottom Side:
  text "'.Layer_Name'" at 89,55.022 h2

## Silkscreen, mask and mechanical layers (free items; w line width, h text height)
Top Overlay:
  text "'.Layer_Name'" at 89,45.375 h2
  text "maxon" at 13.6,17.7 h2
  text "ESCON2 EB Nano" at 13.6,15.7 h2
  text "834838" at 13.6,13.7 h2
Bottom Overlay:
  lines w0.2: 14.9,31.8 14.9,49.65 25.75,49.65 ; 20.05,26.65 30.9,26.65 30.9,44.5 ; 21.2,25.5 21.2,43.35 32.05,43.35 ; 26.35,20.35 37.2,20.35 37.2,38.2
  text "Threaded Hole Mount" at 13.625,44.2 h1.5 r90
  text "'.Layer_Name'" at 89,43.375 h2
  text "Through Hole Mount" at 38.475,25.35 h1.5 r270
  text "ESCON2 Nano 24/2" at 33.95,17.675 h2
Top Paste:
  text "'.Layer_Name'" at 89,49.355 h2
Bottom Paste:
  text "'.Layer_Name'" at 89,47.02 h2
Top Solder:
  text "'.Layer_Name'" at 89,53.355 h2
Bottom Solder:
  text "maxon" at 37.55,67 h2
  text "'.PCB unassembled'-'.PCB Eng Rev'" at 37.55,65 h2
  text "'.Layer_Name'" at 89,51.022 h2
Board:
  the board outline again, w0.1
  text "'.Layer_Name'" at 89,41.02 h2
Dimensions:
  text "'.Layer_Name'" at 89,39.02 h2
Sheet:
  drawing of 22 lines, arcs and shapes, not listed
  text "'.Layer_Name'" at 89,11.022 h2
  text "'.Application_BuildNumber'" at 0.475,-26.712 h1.5
  text "PCB P/N" at 40.728,-26.958 h2.5
  text "date:" at 8.529,-27.15 h2
  text "name:" at 23.479,-27.15 h2
  text "created" at 0.004,-29.848 h2
  text "17.10.2023" at 8.404,-30.075 h3
  text "ADHA" at 23.341,-30.075 h3
  text "'.PCB unassembled'-'.PCB Eng Rev'" at 41.054,-31.725 h6
  text "modified" at 0.004,-32.896 h2
  text "29.04.2024" at 8.404,-33.114 h3
  text "HIN" at 23.341,-33.114 h3
  text "Fabrication Data and Revision" at 40.728,-35.085 h2.5
  text "Date" at 97.63,-35.11 h2.5
  text "reviewed" at 0.004,-35.946 h2
  text "06.05.2024" at 8.404,-36.164 h3
  text "WAH" at 23.341,-36.164 h3
  text "'.Print_Date'" at 98.13,-37.81 h2.5
  text "CO-no." at 0.104,-39.377 h2.5
  text "'.CO_no'" at 7.904,-39.4 h3
  text "'.Print_Time'" at 98.13,-40.035 h2.5
  text "'.ItemAndRevision'" at 41.054,-40.275 h6
  text "Variant P/N" at 40.73,-44.685 h2.5
  text "'.VariantName'" at 40.815,-48.52 h5.4
  text "File:" at 40.604,-52.7 h2.5
  text ".Department" at 16.279,-52.775 h3
  text "'.Pcb_File_Name_No_Path'" at 45.28,-52.785 h2.5
Assembly Notes:
  text "'.Layer_Name'" at 88.998,-4.625 h2
Fab Notes:
  text "'.Layer_Name'" at 89,-6.98 h2
V Cut:
  text "'.Layer_Name'" at 89.002,33.022 h2
Design Notes:
  text "Stapelhöhe 1.5mm bei Platzierung der Bauteile auf Bottom beachten!" at 24.125,-3.888 h0.6
  text "LB-Breite Power: 1mm min., 2-3mm opt." at 24.125,-4.894 h0.6
  text "Anzahl Vias Power: THT 2Stk. min., 2-4Stk. opt. Micro 6-8Stk. min., 12-18Stk. opt." at 24.125,-5.894 h0.6
  text "LB-Breite 5V0, 3V3: 0.15mm min., 0.2mm opt." at 24.125,-6.894 h0.6
Top Assembly:
  text "'.Layer_Name'" at 89,27.375 h2
Bottom Assembly:
  text "'.Layer_Name'" at 89,25.375 h2
Top 3D Body:
  text "'.Layer_Name'" at 89,23.375 h2
Bottom 3D Body:
  text "'.Layer_Name'" at 89,21.375 h2
Top Courtyard:
  text "'.Layer_Name'" at 89,15.375 h2
Bottom Courtyard:
  text "'.Layer_Name'" at 89,13.375 h2
Top Component Outline:
  text "'.Layer_Name'" at 89,19.355 h2
Bottom Component Outline:
  text "'.Layer_Name'" at 89,17.355 h2
Top Terminal:
  text "'.Layer_Name'" at 89,9.355 h2
Bottom Terminal:
  text "'.Layer_Name'" at 89,7.02 h2
Top Test:
  text "'.Layer_Name'" at 89,5.355 h2
Bottom Test:
  text "'.Layer_Name'" at 89,3.02 h2
Top Thermal:
  text "'.Layer_Name'" at 89,1.355 h2
Bottom Thermal:
  text "'.Layer_Name'" at 89,-0.98 h2
Top Coating:
  text "'.Layer_Name'" at 89,37.375 h2
Bottom Coating:
  text "'.Layer_Name'" at 89,35.375 h2
Top Designator:
  text "'.Layer_Name'" at 89,31.375 h2
Bottom Designator:
  text "'.Layer_Name'" at 89,29.375 h2
Top Document Header:
  text "PCB P/N: '.PCB_raw'" at 89,-11 h2
  text "'.ItemAndRevision'" at 89,-12.98 h2
  text "Variant: '.VariantName'" at 89,-15 h2
  text "Variant Name: '.Variant_Description'" at 89,-17 h2
Bottom Document Header:
  text "PCB P/N: '.PCB_raw'" at 104.7,-11 h2
  text "'.ItemAndRevision'" at 104.7,-13 h2
  text "Variant: '.VariantName'" at 104.7,-15 h2
  text "Variant Name: '.Variant_Description'" at 104.7,-17 h2
Auxiliary Line:
  text "'.Layer_Name'" at 88.998,-2.625 h2

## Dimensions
0,0 to 34.9,41.05 on Dimensions
0,0 to 23.5,22.65 on Dimensions
0,70 to 34.9,41.05 on Dimensions
0,70 to 23.5,22.65 on Dimensions
62,65 to 68.467,65 on Dimensions
2.5,59 to 0.314,61.186 on Dimensions
0,0 to 28.6,47.35 on Dimensions
0,0 to 17.2,28.95 on Dimensions
0,70 to 17.2,28.95 on Dimensions
0,70 to 28.6,47.35 on Dimensions
0,0 to 67,0 on Dimensions
0,0 to 54.525,11.775 on Dimensions
0,0 to 62,65 on Dimensions
0,70 to 2.5,59 on Dimensions
0,0 to 5,65 on Dimensions
0,0 to 2.5,59 on Dimensions
0,0 to 54.525,11.775 on Dimensions
0,0 to 0,70 on Dimensions
0,0 to 62,65 on Dimensions
0,0 to 62,5 on Dimensions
